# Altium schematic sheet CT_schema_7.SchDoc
size 287 x 160 mm
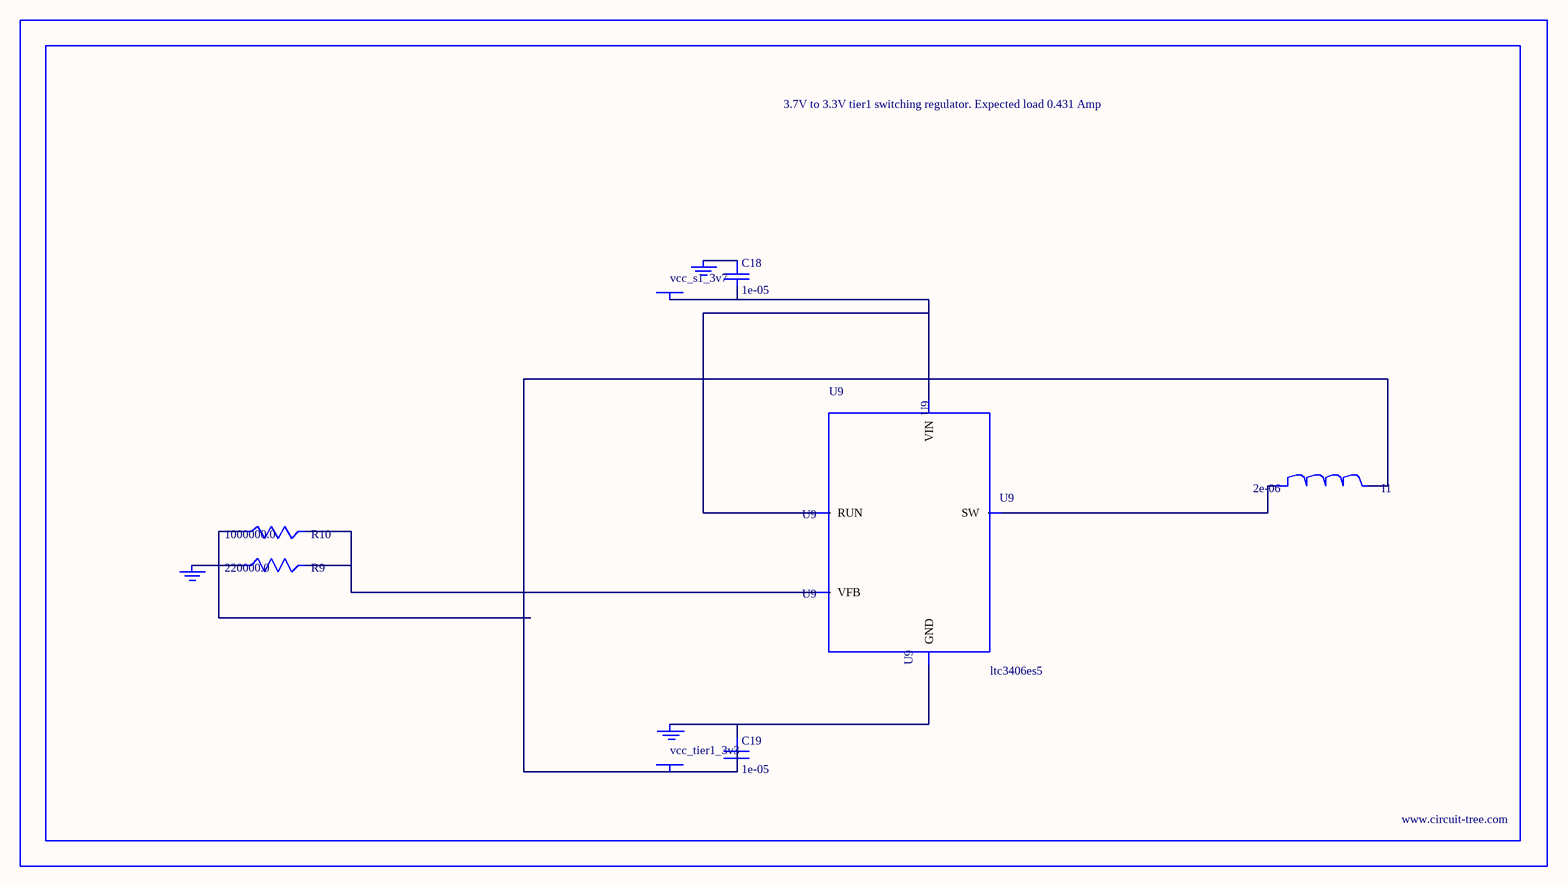
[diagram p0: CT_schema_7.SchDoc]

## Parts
BORDER6  (no value)
C18  1e-05  [C0805]
C19  1e-05  [C0805]
GND_INSTANCE_6_0  (no value)
GND_INSTANCE_6_1  (no value)
GND_INSTANCE_6_2  (no value)
I1  2e-06  [WE-HCI_7030/7040/7050]
POWER_INSTANCE_6_0  vcc_tier1_3v3
POWER_INSTANCE_6_1  vcc_s1_3v7
R9  220000.0  [R0603]
R10  1000000.0  [R0603]
U9  ltc3406es5  [TSOT-23-5]

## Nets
NetC18_1: C18.1 GND_INSTANCE_6_1.0(GND)
NetC18_2: C18.2 POWER_INSTANCE_6_1.0(PWR) U9.1(RUN) U9.4(VIN)
NetC19_1: C19.1 GND_INSTANCE_6_0.0(GND) U9.2(GND)
NetC19_2: C19.2 I1.2 POWER_INSTANCE_6_0.0(PWR) R10.1
NetGND_INSTANCE_6_2_0: GND_INSTANCE_6_2.0(GND) R9.1
NetI1_1: I1.1 U9.3(SW)
NetR9_2: R9.2 R10.2 U9.5(VFB)

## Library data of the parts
BORDER6 = BORDER_PAGE6
C18 C19 = C0805C106K8RACTU
GND_INSTANCE_6_0-GND_INSTANCE_6_2 = GND
I1 = 744314200
POWER_INSTANCE_6_0 POWER_INSTANCE_6_1 = PWR
R9 = RC0603JR-07220KL
R10 = RC0603JR-071ML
